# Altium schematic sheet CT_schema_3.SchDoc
size 395 x 205 mm
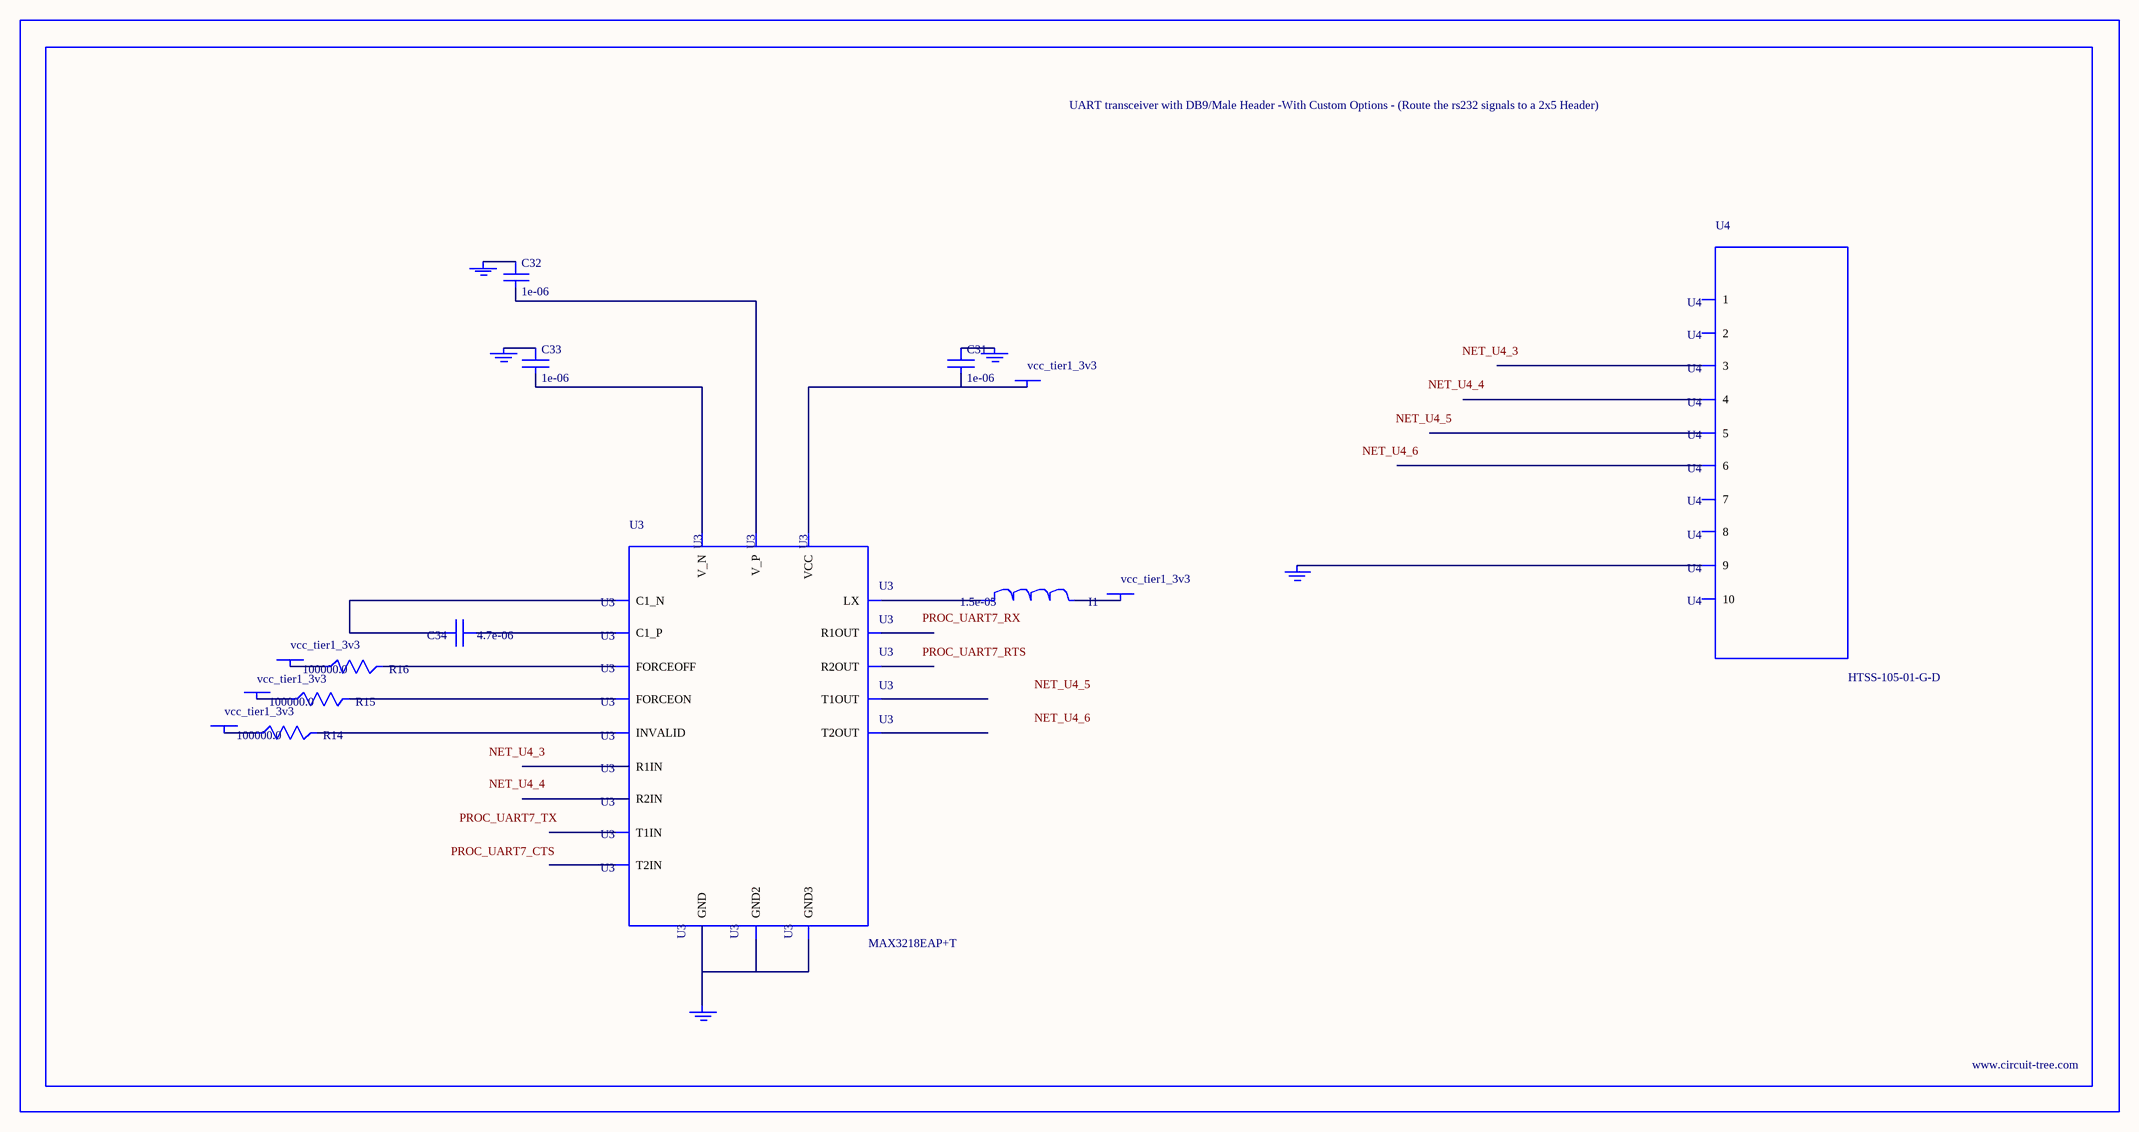
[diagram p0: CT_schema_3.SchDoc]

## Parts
BORDER2  (no value)
C31  1e-06  [C0603]
C32  1e-06  [C0603]
C33  1e-06  [C0603]
C34  4.7e-06  [C0805]
GND_INSTANCE_2_0  (no value)
GND_INSTANCE_2_1  (no value)
GND_INSTANCE_2_2  (no value)
GND_INSTANCE_2_3  (no value)
GND_INSTANCE_2_4  (no value)
I1  1.5e-05  [L1210]
POWER_INSTANCE_2_0  vcc_tier1_3v3
POWER_INSTANCE_2_1  vcc_tier1_3v3
POWER_INSTANCE_2_2  vcc_tier1_3v3
POWER_INSTANCE_2_3  vcc_tier1_3v3
POWER_INSTANCE_2_4  vcc_tier1_3v3
R14  100000.0  [R0603]
R15  100000.0  [R0603]
R16  100000.0  [R0603]
U3  MAX3218EAP+T  [SSOP-20]
U4  HTSS-105-01-G-D  [HTSS-105-01-G-D]

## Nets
NetC31_1: C31.1 GND_INSTANCE_2_0.0(GND)
NetC31_2: C31.2 POWER_INSTANCE_2_4.0(PWR) U3.6(VCC)
NetC32_1: C32.1 GND_INSTANCE_2_2.0(GND)
NetC32_2: C32.2 U3.19(V_P)
NetC33_1: C33.1 GND_INSTANCE_2_1.0(GND)
NetC33_2: C33.2 U3.15(V_N)
NetC34_1: C34.1 U3.18(C1_P)
NetC34_2: C34.2 U3.16(C1_N)
NetGND_INSTANCE_2_3_0: GND_INSTANCE_2_3.0(GND) U3.5(GND) U3.17(GND2) U3.20(GND3)
NetGND_INSTANCE_2_4_0: GND_INSTANCE_2_4.0(GND) U4.9
NetI1_1: I1.1 U3.1(LX)
NetI1_2: I1.2 POWER_INSTANCE_2_0.0(PWR)
NetPOWER_INSTANCE_2_1_0: POWER_INSTANCE_2_1.0(PWR) R14.1
NetPOWER_INSTANCE_2_2_0: POWER_INSTANCE_2_2.0(PWR) R15.1
NetPOWER_INSTANCE_2_3_0: POWER_INSTANCE_2_3.0(PWR) R16.1
NetR14_2: R14.2 U3.2(INVALID)
NetR15_2: R15.2 U3.3(FORCEON)
NetR16_2: R16.2 U3.4(FORCEOFF)

Not connected (* = marked no-connect by the designer): U3 7(T1IN) 8(T2IN) 9(R1OUT) 10(R2OUT) 11(R2IN) 12(R1IN) 13(T2OUT) 14(T1OUT); U4 1 2 3 4 5 6 7 8 10

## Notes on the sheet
- Labels drawn without touching a wire or pin: NET_U4_3, NET_U4_4, NET_U4_5, NET_U4_6, PROC_UART7_CTS, PROC_UART7_RTS, PROC_UART7_RX, PROC_UART7_TX

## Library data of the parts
BORDER2 = BORDER_PAGE2
C31-C33 = C0603C105K3RACTU
C34 = C0805C475K4RACTU
GND_INSTANCE_2_0-GND_INSTANCE_2_4 = GND
I1 = L1210R150MDWIT
POWER_INSTANCE_2_0-POWER_INSTANCE_2_4 = PWR
R14-R16 = RC0603JR-07100KL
